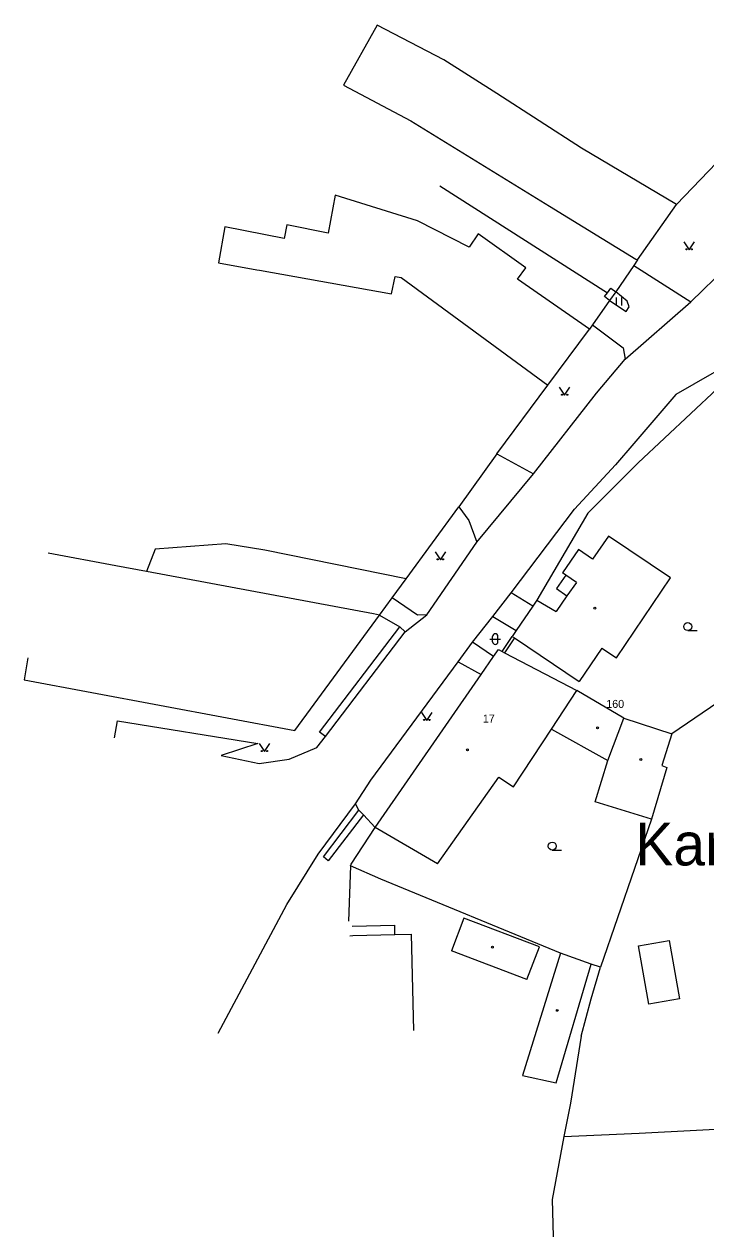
# Model space of a CAD drawing. Extents: x -836739 to -834468, y -1071001 to -1070126.
# Drawn here: x -836738.8 to -836674.9, y -1070409.4 to -1070296.6 of the extents above; entities that cross this region are included whole.
import ezdxf

# ---------------------------------------------------------------- set-up
doc = ezdxf.new("R2010")
doc.units = 0
for name, color, linetype in [('f001_pol_linie', 7, 'Continuous'), ('f001_pol_texty', 7, 'Continuous'), ('f001_pol_znacky', 7, 'Continuous')]:
    doc.layers.add(name, color=color, linetype=linetype)

msp = doc.modelspace()

# ---------------------------------------------------------------- linework, layer by layer
at = {"layer": 'f001_pol_linie'}
for points in [[(-836677.67, -1070313.46), (-836686.56, -1070308.19), (-836694.49, -1070303.06), (-836699.45, -1070299.91), (-836705.71, -1070296.67), (-836708.87, -1070302.29), (-836702.55, -1070305.63), (-836689.57, -1070313.63), (-836681.47, -1070318.57), (-836681.32, -1070318.66)], [(-836703.09, -1070353.49), (-836701.06, -1070351.9), (-836696.37, -1070345.09), (-836691.07, -1070338.71), (-836685.16, -1070331.14), (-836682.48, -1070327.94), (-836676.32, -1070322.57), (-836669.65, -1070316.08), (-836666.36, -1070313.03), (-836662.49, -1070307.65), (-836660.63, -1070303.86), (-836659.99, -1070300.78), (-836660.08, -1070298.96), (-836660.27, -1070297.93), (-836660.82, -1070296.56)], [(-836673.91, -1070309.57), (-836677.67, -1070313.46)], [(-836685.82, -1070325.13), (-836692.58, -1070320.46), (-836691.78, -1070319.4), (-836696.26, -1070316.21), (-836697.09, -1070317.45), (-836701.93, -1070314.99), (-836709.63, -1070312.58), (-836710.31, -1070316.14), (-836714.16, -1070315.38), (-836714.41, -1070316.66), (-836719.98, -1070315.57), (-836720.57, -1070318.93), (-836716.98, -1070319.57), (-836716.72, -1070319.62), (-836704.36, -1070321.83), (-836704.01, -1070320.21), (-836703.45, -1070320.31), (-836689.71, -1070330.38), (-836685.82, -1070325.13)], [(-836699.83, -1070311.72), (-836684.15, -1070321.75)], [(-836681.32, -1070318.66), (-836677.67, -1070313.46)], [(-836681.32, -1070318.66), (-836681.68, -1070319.19), (-836683.37, -1070321.65)], [(-836681.68, -1070319.19), (-836676.32, -1070322.57)], [(-836683.95, -1070322.45), (-836684.41, -1070322.09), (-836684.15, -1070321.75), (-836683.81, -1070321.31), (-836683.37, -1070321.65), (-836683.95, -1070322.45)], [(-836683.95, -1070322.45), (-836682.4, -1070323.48), (-836682.12, -1070323.06), (-836682.29, -1070322.51), (-836683.37, -1070321.65)], [(-836683.95, -1070322.45), (-836685.55, -1070324.74), (-836685.82, -1070325.13)], [(-836685.55, -1070324.74), (-836682.66, -1070326.89), (-836682.48, -1070327.94)], [(-836650.41, -1070367.5), (-836650.96, -1070367.6), (-836651.27, -1070368.67), (-836650.69, -1070374.42), (-836654.63, -1070374.88), (-836655.63, -1070367.52), (-836657.37, -1070353.48), (-836657.73, -1070349.93), (-836659.71, -1070341.92), (-836662.66, -1070333.84), (-836664.35, -1070331.52), (-836667.79, -1070329.01), (-836670.76, -1070327.26), (-836677.72, -1070331.28), (-836681.67, -1070335.86), (-836683.38, -1070337.84)], [(-836694.49, -1070336.82), (-836689.71, -1070330.38)], [(-836661.2, -1070342.3), (-836660.26, -1070341.85), (-836662.88, -1070334.18), (-836673.87, -1070330.74), (-836681.27, -1070337.68)], [(-836694.49, -1070336.82), (-836698.07, -1070341.8)], [(-836694.49, -1070336.82), (-836691.07, -1070338.71)], [(-836681.27, -1070337.68), (-836685.97, -1070342.37), (-836690.74, -1070350.53)], [(-836687.22, -1070342.02), (-836683.38, -1070337.84)], [(-836705.49, -1070351.93), (-836704.32, -1070350.33), (-836703, -1070348.53), (-836698.07, -1070341.8)], [(-836698.07, -1070341.8), (-836697.12, -1070343.08), (-836696.37, -1070345.09)], [(-836706.29, -1070367.39), (-836698.13, -1070356.3), (-836696.77, -1070354.47), (-836694.88, -1070352.08), (-836693.17, -1070349.86), (-836687.22, -1070342.02)], [(-836703, -1070348.53), (-836716.23, -1070345.86), (-836719.88, -1070345.27), (-836726.51, -1070345.77), (-836727.33, -1070347.85)], [(-836684.04, -1070344.53), (-836685.54, -1070346.69)], [(-836678.22, -1070348.45), (-836684.04, -1070344.53)], [(-836705.49, -1070351.93), (-836706.04, -1070351.83), (-836727.33, -1070347.85), (-836730.19, -1070347.31), (-836736.52, -1070346.13)], [(-836686.84, -1070345.79), (-836688.34, -1070347.97)], [(-836685.54, -1070346.69), (-836686.84, -1070345.79)], [(-836688.04, -1070348.18), (-836688.92, -1070349.45), (-836687.93, -1070350.14)], [(-836687.05, -1070348.87), (-836688.04, -1070348.18), (-836688.34, -1070347.97)], [(-836683.3, -1070355.94), (-836678.22, -1070348.45)], [(-836691.13, -1070351.1), (-836693.17, -1070349.86)], [(-836687.05, -1070348.87), (-836687.93, -1070350.14), (-836688.95, -1070351.61)], [(-836658.62, -1070349.8), (-836678.12, -1070363.07)], [(-836701.06, -1070351.9), (-836701.93, -1070351.93), (-836704.32, -1070350.33)], [(-836690.74, -1070350.53), (-836691.13, -1070351.1), (-836692.68, -1070353.37), (-836693.06, -1070353.93)], [(-836690.74, -1070350.53), (-836688.95, -1070351.61)], [(-836713.42, -1070362.75), (-836705.49, -1070351.93)], [(-836705.49, -1070351.93), (-836703.58, -1070353.02)], [(-836694.88, -1070352.08), (-836692.68, -1070353.37)], [(-836710.55, -1070363.3), (-836711.11, -1070362.89), (-836703.58, -1070353.02), (-836703.09, -1070353.49)], [(-836710.55, -1070363.3), (-836703.09, -1070353.49)], [(-836694, -1070355.34), (-836693.06, -1070353.93)], [(-836692.85, -1070354.07), (-836693.78, -1070355.46)], [(-836693.06, -1070353.93), (-836692.85, -1070354.07), (-836686.78, -1070358.17)], [(-836705.9, -1070371.82), (-836695.98, -1070357.51), (-836694.81, -1070355.82), (-836694.35, -1070355.16)], [(-836694.81, -1070355.82), (-836696.77, -1070354.47)], [(-836694.35, -1070355.16), (-836694, -1070355.34), (-836693.78, -1070355.46), (-836687.01, -1070359.01)], [(-836684.66, -1070355.02), (-836686.78, -1070358.17)], [(-836684.66, -1070355.02), (-836683.3, -1070355.94)], [(-836738.43, -1070355.93), (-836738.78, -1070358.01), (-836713.42, -1070362.75)], [(-836698.13, -1070356.3), (-836695.98, -1070357.51)], [(-836700.07, -1070375.25), (-836694.32, -1070367.11), (-836692.94, -1070368.01), (-836689.38, -1070362.61), (-836687.01, -1070359.01)], [(-836682.62, -1070361.58), (-836687.01, -1070359.01)], [(-836730.3, -1070363.44), (-836730.03, -1070361.83), (-836716.89, -1070363.98), (-836720.32, -1070365.08)], [(-836679.04, -1070366.04), (-836678.57, -1070366.2), (-836680, -1070371.07), (-836685.28, -1070369.42), (-836684.11, -1070365.55), (-836682.62, -1070361.58), (-836678.12, -1070363.07), (-836679.04, -1070366.04)], [(-836720.32, -1070365.08), (-836716.75, -1070365.84), (-836713.94, -1070365.44), (-836711.35, -1070364.34), (-836710.55, -1070363.3)], [(-836689.38, -1070362.61), (-836684.11, -1070365.55)], [(-836720.59, -1070391.12), (-836714.17, -1070379.05), (-836711.25, -1070374.34), (-836707.73, -1070369.63), (-836706.29, -1070367.39)], [(-836707.42, -1070370.22), (-836707.73, -1070369.63)], [(-836707.42, -1070370.22), (-836706.99, -1070370.64), (-836710.29, -1070374.97), (-836710.74, -1070374.58), (-836707.42, -1070370.22)], [(-836705.9, -1070371.82), (-836706.99, -1070370.64)], [(-836680, -1070371.07), (-836684.8, -1070384.91)], [(-836708.14, -1070375.26), (-836705.9, -1070371.82)], [(-836700.07, -1070375.25), (-836705.9, -1070371.82)], [(-836708.22, -1070375.44), (-836708.38, -1070380.61)], [(-836708.22, -1070375.44), (-836708.14, -1070375.26)], [(-836688.53, -1070383.6), (-836705.37, -1070376.67), (-836708.22, -1070375.44)], [(-836697.58, -1070380.33), (-836698.76, -1070383.4)], [(-836690.52, -1070383.01), (-836697.58, -1070380.33)], [(-836708.05, -1070381.07), (-836704.06, -1070380.98)], [(-836704.04, -1070381.87), (-836704.06, -1070380.98)], [(-836708.28, -1070381.97), (-836708, -1070381.96), (-836704.04, -1070381.87), (-836702.54, -1070381.84)], [(-836702.54, -1070381.84), (-836702.31, -1070390.86)], [(-836677.4, -1070387.88), (-836680.27, -1070388.39), (-836681.23, -1070382.92), (-836678.37, -1070382.42), (-836677.4, -1070387.88)], [(-836691.69, -1070386.08), (-836698.76, -1070383.4)], [(-836688.94, -1070395.76), (-836685.66, -1070384.65), (-836688.53, -1070383.6), (-836692.11, -1070395.08), (-836688.94, -1070395.76)], [(-836691.69, -1070386.08), (-836690.52, -1070383.01)], [(-836686.61, -1070391.4), (-836685.67, -1070387.88), (-836684.8, -1070384.91), (-836685.66, -1070384.65)], [(-836686.61, -1070391.4), (-836687.61, -1070397.67), (-836688.21, -1070400.8), (-836689.33, -1070406.69), (-836688.98, -1070419.42), (-836689, -1070419.82)], [(-836688.21, -1070400.8), (-836681.18, -1070400.48), (-836671.03, -1070399.94), (-836657.89, -1070399.1)]]:
    msp.add_lwpolyline(points, dxfattribs=at)
at = {"layer": 'f001_pol_znacky'}
for p, q in [((-836683.29, -1070322.94), (-836683.29, -1070322.19)), ((-836682.79, -1070322.94), (-836682.79, -1070322.19)), ((-836695.15, -1070354.18), (-836694.15, -1070354.18)), ((-836694.9, -1070354.43), (-836694.9, -1070353.93)), ((-836694.4, -1070354.43), (-836694.4, -1070353.93)), ((-836676.62, -1070353.39), (-836675.74, -1070353.39)), ((-836689.31, -1070373.96), (-836688.44, -1070373.96))]:
    msp.add_line(p, q, dxfattribs=at)
for points in [[(-836676.99, -1070316.96), (-836676.49, -1070317.71), (-836675.99, -1070316.96)], [(-836688.65, -1070330.59), (-836688.15, -1070331.34), (-836687.65, -1070330.59)], [(-836700.29, -1070346.01), (-836699.79, -1070346.76), (-836699.29, -1070346.01)], [(-836701.56, -1070361.06), (-836701.06, -1070361.81), (-836700.56, -1070361.06)], [(-836716.77, -1070363.97), (-836716.27, -1070364.72), (-836715.77, -1070363.97)]]:
    msp.add_lwpolyline(points, dxfattribs=at)
for centre, radius in [((-836676.74, -1070317.66), 0.05), ((-836676.24, -1070317.66), 0.05), ((-836688.4, -1070331.29), 0.05), ((-836687.9, -1070331.29), 0.05), ((-836700.04, -1070346.71), 0.05), ((-836699.54, -1070346.71), 0.05), ((-836685.33, -1070351.29), 0.0875), ((-836676.62, -1070353.01), 0.375), ((-836701.31, -1070361.76), 0.05), ((-836700.81, -1070361.76), 0.05), ((-836685.06, -1070362.5), 0.0875), ((-836697.26, -1070364.55), 0.0875), ((-836716.52, -1070364.67), 0.05), ((-836716.02, -1070364.67), 0.05), ((-836681.01, -1070365.46), 0.0875), ((-836689.31, -1070373.58), 0.375), ((-836694.92, -1070383.04), 0.0875), ((-836688.84, -1070388.97), 0.0875)]:
    msp.add_circle(centre, radius, dxfattribs=at)
for centre, start, end in [((-836694.65, -1070353.93), 0, 180), ((-836694.65, -1070354.43), 180, 360)]:
    msp.add_arc(centre, 0.25, start, end, dxfattribs=at)

# ---------------------------------------------------------------- texts
at = {"layer": 'f001_pol_texty'}
for s, height, p in [('160', 0.75, (-836684.25, -1070360.63)), ('17', 0.75, (-836695.81, -1070362)), ('Kamenný Újezd', 4, (-836681.54, -1070375.39))]:
    msp.add_text(s, height=height, dxfattribs=at).set_placement(p)

doc.saveas('drawing.dxf')
